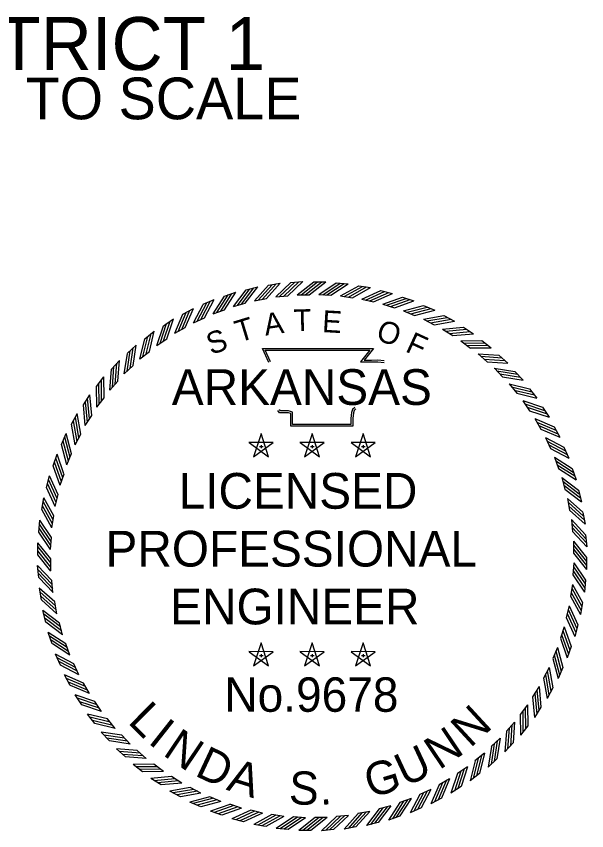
# Model space of a CAD drawing. Extents: x -31696 to 27919, y -8775 to 11152.
# Drawn here: x 13014 to 15598, y -7140 to -3450 of the extents above; entities that cross this region are included whole.
import ezdxf

# ---------------------------------------------------------------- set-up
doc = ezdxf.new("R2010")
doc.units = 0
for name, color, linetype in [('Level 2', 7, 'Continuous'), ('Level 48', 7, 'Continuous'), ('Level 52', 7, 'Continuous')]:
    doc.layers.add(name, color=color, linetype=linetype)

msp = doc.modelspace()

# ---------------------------------------------------------------- linework, layer by layer
at = {"layer": 'Level 52'}
for p, q in [((14055.5, -4689.3), (14108.2, -4675.5)), ((14156.1, -4668.8), (14209.8, -4659.3)), ((14258.1, -4656.6), (14312.3, -4651.6)), ((14361.3, -4653.6), (14415.8, -4653.6)), ((14463.3, -4657.6), (14517.7, -4661.6)), ((14565.2, -4670.9), (14619, -4679.3)), ((13956.9, -4718.2), (14008.3, -4700)), ((14189.4, -4721.2), (14243.8, -4716.1)), ((14286.9, -4711.5), (14341.5, -4711.5)), ((14384.9, -4710), (14439.4, -4714)), ((14482.7, -4716.6), (14536.7, -4725.1)), ((14665.6, -4692.5), (14718.5, -4705.3)), ((14763.9, -4722.3), (14815.6, -4739.5)), ((13861, -4755), (13910.7, -4732.7)), ((13998.3, -4764.3), (14051.1, -4750.4)), ((14093, -4738.8), (14146.7, -4729.3)), ((14579.6, -4731.2), (14632.7, -4744.1)), ((14675, -4753.8), (14726.8, -4771)), ((13768.5, -4799.6), (13816.2, -4773.3)), ((13906.1, -4797.6), (13957.6, -4779.4)), ((14768.2, -4784.2), (14818.4, -4805.6)), ((14859.4, -4760.1), (14909.5, -4781.5)), ((13680, -4851.8), (13725.4, -4821.5)), ((13817, -4838.4), (13866.8, -4816)), ((14858.6, -4822.1), (14906.8, -4847.7)), ((14951.4, -4805.7), (14999.6, -4831.2)), ((13731.5, -4886.4), (13779.3, -4859.9)), ((14945.5, -4867.4), (14991.5, -4896.9)), ((15039.4, -4858.7), (15085.3, -4888.1)), ((13596.1, -4911), (13638.8, -4877.2)), ((13517.4, -4977), (13557.2, -4939.7)), ((13650.3, -4941.2), (13695.8, -4911)), ((15028.4, -4919.8), (15071.8, -4952.9)), ((15122.7, -4918.8), (15166, -4951.9)), ((13573.9, -5002.6), (13616.7, -4968.7)), ((15106.6, -4978.7), (15147.2, -5015.4)), ((13444.4, -5049.2), (13481, -5008.8)), ((15200.7, -4985.6), (15241.1, -5022.1)), ((13502.8, -5070.1), (13542.7, -5032.8)), ((15179.8, -5044), (15217.1, -5083.8)), ((13377.7, -5127.3), (13410.7, -5084)), ((15272.9, -5058.6), (15310.2, -5098.3)), ((13437.6, -5143.3), (13474.2, -5102.8)), ((15247.3, -5115.1), (15281.2, -5157.8)), ((13317.5, -5210.6), (13346.9, -5164.7)), ((15338.9, -5137.3), (15372.8, -5180)), ((13378.6, -5221.6), (13411.8, -5178.2)), ((15308.7, -5191.5), (15339, -5236.9)), ((15398.2, -5221.2), (15428.4, -5266.5)), ((13264.5, -5298.5), (13290, -5250.4)), ((13326.3, -5304.4), (13355.7, -5258.4)), ((15363.6, -5272.7), (15390, -5320.5)), ((15450.3, -5309.7), (15476.7, -5357.4)), ((13218.9, -5390.6), (13240.4, -5340.5)), ((13281, -5391.4), (13306.5, -5343.1)), ((14123.2, -5341), (14089.1, -5445.6)), ((14157.1, -5445.5), (14123.2, -5340.9)), ((14354.3, -5341), (14320.2, -5445.6)), ((14388.2, -5445.5), (14354.4, -5340.9)), ((14585.4, -5341), (14551.3, -5445.6)), ((14619.4, -5445.5), (14585.5, -5340.9)), ((14178.1, -5380.9), (14068.1, -5380.8)), ((14068.2, -5380.9), (14157.2, -5445.7)), ((14089.2, -5445.5), (14178.3, -5381)), ((14409.2, -5380.9), (14299.2, -5380.8)), ((14299.3, -5380.9), (14388.3, -5445.7)), ((14320.3, -5445.5), (14409.4, -5381)), ((14640.4, -5380.9), (14530.4, -5380.8)), ((14530.5, -5380.9), (14619.4, -5445.7)), ((14551.4, -5445.5), (14640.5, -5381)), ((15411.6, -5358.1), (15434, -5407.9)), ((14115.3, -5398.5), (14131.7, -5398.5)), ((14123.3, -5392.6), (14123.3, -5406.4)), ((14346.5, -5398.5), (14362.8, -5398.5)), ((14354.4, -5392.6), (14354.4, -5406.4)), ((14577.6, -5398.5), (14593.9, -5398.5)), ((14585.5, -5392.6), (14585.5, -5406.4)), ((15494.9, -5402.2), (15517.3, -5451.9)), ((13181.1, -5486), (13198.3, -5434.4)), ((13243, -5481.7), (13264.5, -5431.5)), ((15452.3, -5447.3), (15470.5, -5498.8)), ((13151.3, -5584.3), (13164.2, -5531.4)), ((13212.6, -5574.9), (13229.9, -5523.1)), ((15531.8, -5498), (15549.9, -5549.4)), ((15485.6, -5539.5), (15499.5, -5592.3)), ((15560.6, -5596.6), (15574.4, -5649.3)), ((13129.7, -5684.7), (13138.2, -5630.9)), ((13190.1, -5670.3), (13203, -5617.2)), ((15511.1, -5634.1), (15520.6, -5687.9)), ((13175.4, -5767.2), (13183.9, -5713.3)), ((15581.1, -5697.3), (15590.6, -5750.9)), ((13116.5, -5786.6), (13120.5, -5732.3)), ((15528.8, -5730.5), (15533.8, -5784.9)), ((13168.9, -5865), (13172.9, -5810.5)), ((15538.4, -5828.1), (15538.9, -5882.7)), ((15593.3, -5799.2), (15598.3, -5853.5)), ((13111.7, -5889.2), (13111.2, -5834.7)), ((15597.1, -5901.9), (15597.6, -5956.4)), ((13115.5, -5991.8), (13110.5, -5937.6)), ((13170.4, -5963), (13169.9, -5908.4)), ((15539.9, -5926.1), (15535.9, -5980.5)), ((13180, -6060.6), (13175, -6006.2)), ((15592.3, -6004.5), (15588.3, -6058.8)), ((13127.6, -6093.8), (13118.2, -6040.2)), ((15533.3, -6023.9), (15524.9, -6077.8)), ((13197.6, -6157), (13188.2, -6103.2)), ((15518.7, -6120.8), (15505.8, -6173.8)), ((15579.1, -6106.3), (15570.6, -6160.1)), ((13148.2, -6194.4), (13134.3, -6141.8)), ((13223.2, -6251.6), (13209.3, -6198.8)), ((15496.1, -6216.2), (15478.9, -6268)), ((15557.5, -6206.7), (15544.6, -6259.7)), ((13177, -6293), (13158.8, -6241.7)), ((13256.5, -6343.8), (13238.2, -6292.3)), ((14123.2, -6288.6), (14089.1, -6393.2)), ((14157.1, -6393.1), (14123.2, -6288.5)), ((14354.3, -6288.6), (14320.2, -6393.2)), ((14388.2, -6393.1), (14354.4, -6288.5)), ((14585.4, -6288.6), (14551.3, -6393.2)), ((14619.4, -6393.1), (14585.5, -6288.5)), ((15527.7, -6305), (15510.4, -6356.7)), ((13213.9, -6388.9), (13191.5, -6339.2)), ((14178.1, -6328.5), (14068.1, -6328.4)), ((14068.2, -6328.5), (14157.2, -6393.3)), ((14089.2, -6393.1), (14178.3, -6328.6)), ((14123.3, -6340.2), (14123.3, -6354)), ((14409.2, -6328.5), (14299.2, -6328.4)), ((14299.3, -6328.5), (14388.3, -6393.3)), ((14320.3, -6393.1), (14409.4, -6328.6)), ((14354.4, -6340.2), (14354.4, -6354)), ((14640.4, -6328.5), (14530.4, -6328.4)), ((14530.5, -6328.5), (14619.4, -6393.3)), ((14551.4, -6393.1), (14640.5, -6328.6)), ((14585.5, -6340.2), (14585.5, -6354)), ((15465.8, -6309.4), (15444.3, -6359.6)), ((14115.3, -6346.1), (14131.7, -6346.1)), ((14346.5, -6346.1), (14362.8, -6346.1)), ((14577.6, -6346.1), (14593.9, -6346.1)), ((13297.2, -6432.9), (13274.8, -6383.1)), ((15427.8, -6399.7), (15402.3, -6448)), ((15489.8, -6400.5), (15468.4, -6450.6)), ((13258.5, -6481.4), (13232.1, -6433.7)), ((13345.2, -6518.4), (13318.8, -6470.6)), ((15382.5, -6486.6), (15353.1, -6532.6)), ((15444.3, -6492.6), (15418.8, -6540.7)), ((13310.6, -6569.9), (13280.4, -6524.6)), ((13400.1, -6599.6), (13369.8, -6554.2)), ((15330.2, -6569.5), (15297, -6612.9)), ((15391.2, -6580.5), (15361.9, -6626.4)), ((13369.9, -6653.8), (13336, -6611.1)), ((13461.5, -6676), (13427.6, -6633.2)), ((15271.2, -6647.8), (15234.6, -6688.3)), ((15331.1, -6663.8), (15298.1, -6707.1)), ((13435.8, -6732.5), (13398.6, -6692.8)), ((13529, -6747.1), (13491.6, -6707.2)), ((15205.9, -6720.9), (15166.1, -6758.3)), ((15264.4, -6741.8), (15227.8, -6782.3)), ((13508.1, -6805.5), (13467.7, -6769)), ((13602.1, -6812.3), (13561.6, -6775.7)), ((15134.9, -6788.4), (15092.1, -6822.4)), ((15191.4, -6814.1), (15151.6, -6851.4)), ((13586.1, -6872.3), (13542.8, -6839.2)), ((13680.4, -6871.3), (13637, -6838.2)), ((15058.5, -6849.8), (15013, -6880.1)), ((13763.3, -6923.6), (13717.3, -6894.2)), ((15112.6, -6880.1), (15070, -6913.9)), ((13669.4, -6932.4), (13623.5, -6903)), ((14977.3, -6904.7), (14929.5, -6931.2)), ((13757.4, -6985.4), (13709.2, -6959.9)), ((13850.2, -6968.9), (13801.9, -6943.4)), ((14891.8, -6952.7), (14842, -6975.1)), ((15028.8, -6939.3), (14983.4, -6969.5)), ((13849.4, -7031), (13799.3, -7009.6)), ((13940.6, -7006.9), (13890.4, -6985.4)), ((14802.7, -6993.5), (14751.2, -7011.7)), ((14940.3, -6991.4), (14892.6, -7017.8)), ((14033.8, -7037.3), (13982, -7020)), ((14710.5, -7026.7), (14657.6, -7040.6)), ((14847.8, -7036.1), (14798.1, -7058.4)), ((13944.9, -7068.8), (13893.2, -7051.6)), ((14129.1, -7059.9), (14076.1, -7047)), ((14226.1, -7074.5), (14172.1, -7066)), ((14323.9, -7081.1), (14269.4, -7077.1)), ((14421.9, -7079.5), (14367.3, -7080)), ((14519.4, -7069.9), (14465, -7074.9)), ((14615.8, -7052.3), (14562, -7061.8)), ((14751.9, -7072.9), (14700.5, -7091.1)), ((14043.2, -7098.6), (13990.3, -7085.7)), ((14143.6, -7120.2), (14089.8, -7111.7)), ((14653.3, -7101.7), (14600.6, -7115.6)), ((14245.5, -7133.4), (14191.1, -7129.4)), ((14348.1, -7138.2), (14293.6, -7138.7)), ((14450.7, -7134.5), (14396.4, -7139.5)), ((14552.7, -7122.3), (14499, -7131.8))]:
    msp.add_line(p, q, dxfattribs=at)
for points in [[(14015.3, -4760.1), (14072.4, -4685.1)], [(14033.5, -4754.9), (14090.6, -4679.9)], [(14051.1, -4750.4), (14108.2, -4675.4)], [(14092.9, -4738.9), (14156, -4668.8)], [(14110.2, -4736), (14173.3, -4666)], [(14128.8, -4732.3), (14191.9, -4662.3)], [(14146.7, -4729.3), (14209.8, -4659.3)], [(14189.3, -4721.2), (14258, -4656.7)], [(14206.8, -4719.8), (14275.5, -4655.2)], [(14225.6, -4717.6), (14294.3, -4653.1)], [(14243.7, -4716.1), (14312.4, -4651.6)], [(14286.9, -4711.6), (14361.2, -4653.6)], [(14304.4, -4711.8), (14378.7, -4653.8)], [(14323.3, -4711.3), (14397.7, -4653.4)], [(14341.5, -4711.5), (14415.8, -4653.5)], [(14384.9, -4710.1), (14463.2, -4657.7)], [(14402.3, -4711.5), (14480.7, -4659.1)], [(14421.2, -4712.5), (14499.6, -4660.1)], [(14439.3, -4714), (14517.7, -4661.6)], [(14482.6, -4716.6), (14565.1, -4670.9)], [(14499.9, -4719.5), (14582.4, -4673.8)], [(14518.7, -4722), (14601.2, -4676.3)], [(14536.6, -4725), (14619.1, -4679.3)], [(13906.1, -4797.7), (13956.8, -4718.2)], [(13922.7, -4792), (13973.4, -4712.5)], [(13940.4, -4785.3), (13991.1, -4705.8)], [(13957.5, -4779.4), (14008.3, -4699.9)], [(13998.3, -4764.4), (14055.4, -4689.4)], [(14579.6, -4731.2), (14665.5, -4692.5)], [(14596.6, -4735.5), (14682.5, -4696.8)], [(14615, -4739.6), (14701, -4700.9)], [(14632.6, -4744.1), (14718.6, -4705.3)], [(13817, -4838.4), (13861, -4755.1)], [(13833, -4831.4), (13877, -4748)], [(13850.1, -4823.3), (13894.1, -4739.9)], [(13866.7, -4816), (13910.8, -4732.6)], [(14674.9, -4753.8), (14763.8, -4722.3)], [(14691.5, -4759.5), (14780.4, -4728)], [(14709.6, -4765.1), (14798.5, -4733.6)], [(14726.8, -4771), (14815.6, -4739.5)], [(13746.9, -4878.1), (13783.9, -4791.4)], [(13763.3, -4868.6), (13800.3, -4781.8)], [(13779.2, -4859.9), (13816.2, -4773.2)], [(14768.1, -4784.2), (14859.3, -4760.1)], [(14784.2, -4791.2), (14875.3, -4767.2)], [(14801.8, -4798.3), (14892.9, -4774.2)], [(14818.4, -4805.6), (14909.5, -4781.5)], [(13680.5, -4920.9), (13710.2, -4831.4)], [(13695.7, -4911), (13725.4, -4821.5)], [(13731.5, -4886.4), (13768.5, -4799.7)], [(14858.5, -4822.1), (14951.3, -4805.7)], [(14873.9, -4830.5), (14966.7, -4814)], [(14890.8, -4839), (14983.7, -4822.5)], [(14906.8, -4847.6), (14999.6, -4831.1)], [(13650.3, -4941.3), (13680, -4851.8)], [(13665, -4931.7), (13694.7, -4842.3)], [(14945.4, -4867.4), (15039.3, -4858.7)], [(14960.1, -4877), (15054, -4868.3)], [(13587.7, -4992), (13609.9, -4900.3)], [(13602.3, -4979.9), (13624.5, -4888.2)], [(13616.6, -4968.7), (13638.8, -4877.1)], [(14976.3, -4886.9), (15070.1, -4878.1)], [(14991.4, -4896.8), (15085.3, -4888.1)], [(13542.6, -5032.8), (13557.2, -4939.7)], [(13573.9, -5002.7), (13596.1, -4911.1)], [(15028.3, -4919.8), (15122.6, -4918.8)], [(15042.1, -4930.5), (15136.4, -4929.6)], [(15057.4, -4941.7), (15151.7, -4940.7)], [(13502.8, -5070.2), (13517.4, -4977.1)], [(13515.7, -5058.3), (13530.3, -4965.2)], [(13529.3, -5045.1), (13543.8, -4952)], [(14158.3, -5018.2), (14129.2, -4955.3), (14631.7, -4955), (14589.8, -5007.8), (14623.9, -5007.3), (14652.4, -5007), (14680.9, -5010.1)], [(14165.5, -5014.9), (14141.7, -4963.3), (14615.2, -4963), (14573.1, -5016), (14624, -5015.3), (14652, -5014.9), (14680, -5018)], [(15071.7, -4952.8), (15166, -4951.9)], [(15106.6, -4978.7), (15200.6, -4985.6)], [(13474.1, -5102.8), (13481, -5008.8)], [(15119.5, -4990.6), (15213.5, -4997.4)], [(15133.8, -5003), (15227.8, -5009.8)], [(15147.1, -5015.3), (15241.2, -5022.1)], [(13437.6, -5143.4), (13444.4, -5049.3)], [(13449.5, -5130.5), (13456.3, -5036.4)], [(13461.8, -5116.1), (13468.7, -5022.1)], [(15179.7, -5044), (15272.8, -5058.6)], [(13411.7, -5178.2), (13410.7, -5083.9)], [(15191.6, -5056.9), (15284.7, -5071.5)], [(15204.8, -5070.4), (15298, -5085)], [(15217.1, -5083.8), (15310.3, -5098.3)], [(13378.6, -5221.6), (13377.6, -5127.4)], [(13389.4, -5207.8), (13388.4, -5113.5)], [(13400.5, -5192.5), (13399.6, -5098.2)], [(15247.2, -5115), (15338.8, -5137.3)], [(13355.7, -5258.5), (13346.9, -5164.6)], [(15258, -5128.9), (15349.6, -5151.1)], [(15270.1, -5143.5), (15361.7, -5165.7)], [(15281.2, -5157.8), (15372.8, -5180)], [(13335.9, -5289.8), (13327.1, -5196)], [(13345.7, -5273.7), (13337, -5179.8)], [(15308.6, -5191.4), (15398.1, -5221.1)], [(13326.3, -5304.5), (13317.5, -5210.7)], [(14552.6, -5228.8), (14544, -5235.8), (14541.1, -5246.2), (14538.3, -5272.3), (14538.3, -5307), (14257.8, -5307), (14257.8, -5260.1), (14257.8, -5249.7), (14246.4, -5246.2), (14206.5, -5246.2), (14199.4, -5235.4)], [(14547.5, -5222.6), (14537, -5231.2), (14533.3, -5244.7), (14530.3, -5271.8), (14530.3, -5299), (14265.7, -5299), (14265.7, -5260.1), (14265.7, -5243.8), (14247.6, -5238.2), (14210.8, -5238.2), (14206.1, -5231)], [(15318.2, -5206.1), (15407.7, -5235.8)], [(15329, -5221.6), (15418.5, -5251.3)], [(15339, -5236.8), (15428.5, -5266.5)], [(13297.8, -5359.1), (13281.4, -5266.3)], [(13306.5, -5343.1), (13290, -5250.3)], [(15363.5, -5272.6), (15450.2, -5309.6)], [(13281, -5391.4), (13264.5, -5298.6)], [(13289.3, -5376), (13272.9, -5283.2)], [(15371.8, -5288.1), (15458.6, -5325.1)], [(15381.4, -5304.4), (15468.1, -5341.4)], [(13264.4, -5431.6), (13240.4, -5340.4)], [(15390, -5320.4), (15476.7, -5357.4)], [(13250.1, -5465.7), (13226, -5374.6)], [(13257.1, -5448.2), (13233.1, -5357)], [(15411.5, -5358.1), (15494.9, -5402.1)], [(15418.5, -5374.2), (15501.9, -5418.2)], [(13243, -5481.8), (13219, -5390.7)], [(15426.7, -5391.2), (15510, -5435.3)], [(15434, -5407.9), (15517.3, -5451.9)], [(13223.9, -5540.3), (13192.4, -5451.5)], [(13229.8, -5523.1), (13198.3, -5434.3)], [(15452.3, -5447.2), (15531.7, -5498)], [(13212.7, -5575), (13181.1, -5486.1)], [(13218.4, -5558.4), (13186.8, -5469.6)], [(15458, -5463.8), (15537.4, -5514.6)], [(15464.7, -5481.5), (15544.1, -5532.3)], [(13202.9, -5617.3), (13164.2, -5531.3)], [(15470.6, -5498.7), (15550, -5549.4)], [(13194.4, -5653.4), (13155.7, -5567.4)], [(13198.5, -5634.9), (13159.7, -5548.9)], [(15485.5, -5539.4), (15560.5, -5596.6)], [(15489.8, -5556.4), (15564.8, -5613.6)], [(13190.1, -5670.4), (13151.3, -5584.4)], [(15495.1, -5574.6), (15570, -5631.8)], [(15499.5, -5592.2), (15574.5, -5649.4)], [(13183.9, -5713.3), (13138.2, -5630.9)], [(15511.1, -5634), (15581.1, -5697.2)], [(13178.4, -5750), (13132.7, -5667.5)], [(13180.9, -5731.2), (13135.2, -5648.8)], [(15514, -5651.3), (15584, -5714.5)], [(15517.7, -5669.9), (15587.7, -5733.1)], [(13175.5, -5767.3), (13129.8, -5684.8)], [(15520.6, -5687.8), (15590.7, -5751)], [(13171.3, -5828.7), (13119, -5750.3)], [(13172.8, -5810.6), (13120.5, -5732.2)], [(15528.7, -5730.5), (15593.3, -5799.2)], [(15530.2, -5747.9), (15594.7, -5816.6)], [(13168.9, -5865.1), (13116.5, -5786.7)], [(13170.4, -5847.6), (13118, -5769.2)], [(15532.3, -5766.7), (15596.9, -5835.5)], [(15533.8, -5784.8), (15598.4, -5853.5)], [(15538.3, -5828), (15597, -5901.8)], [(13169.9, -5908.5), (13111.2, -5834.7)], [(13169.9, -5926.6), (13111.2, -5852.8)], [(15538.3, -5845.5), (15597, -5919.3)], [(15538.9, -5864.5), (15597.6, -5938.3)], [(13170.4, -5945.5), (13111.8, -5871.7)], [(13170.4, -5963.1), (13111.8, -5889.3)], [(15538.9, -5882.6), (15597.6, -5956.4)], [(13175, -6006.2), (13110.4, -5937.5)], [(15539.9, -5926), (15592.2, -6004.4)], [(13176.5, -6024.3), (13111.9, -5955.6)], [(13178.6, -6043.1), (13114.1, -5974.4)], [(15537.5, -5962.4), (15589.8, -6040.8)], [(15538.4, -5943.5), (15590.8, -6021.9)], [(13180.1, -6060.6), (13115.5, -5991.9)], [(15536, -5980.5), (15588.3, -6058.9)], [(13188.1, -6103.3), (13118.1, -6040.1)], [(15530.4, -6041.1), (15576.1, -6123.5)], [(15533.3, -6023.8), (15579, -6106.2)], [(13191.1, -6121.2), (13121.1, -6058)], [(13194.8, -6139.7), (13124.8, -6076.6)], [(15524.9, -6077.8), (15570.6, -6160.2)], [(15527.9, -6059.8), (15573.6, -6142.3)], [(13197.7, -6157), (13127.7, -6093.9)], [(15518.7, -6120.7), (15557.4, -6206.7)], [(13209.3, -6198.9), (13134.3, -6141.7)], [(13213.7, -6216.5), (13138.7, -6159.3)], [(15510.3, -6156.2), (15549.1, -6242.1)], [(15514.4, -6137.7), (15553.1, -6223.7)], [(13218.9, -6234.7), (13144, -6177.5)], [(13223.3, -6251.7), (13148.3, -6194.5)], [(15505.9, -6173.8), (15544.6, -6259.7)], [(15490.4, -6232.7), (15521.9, -6321.5)], [(15496.1, -6216.1), (15527.6, -6304.9)], [(13238.2, -6292.4), (13158.8, -6241.6)], [(13244.1, -6309.6), (13164.7, -6258.8)], [(15478.9, -6267.9), (15510.5, -6356.8)], [(15484.8, -6250.8), (15516.4, -6339.6)], [(13250.8, -6327.3), (13171.4, -6276.5)], [(13256.5, -6343.8), (13177.1, -6293.1)], [(13274.8, -6383.2), (13191.5, -6339.2)], [(15451.6, -6342.9), (15475.7, -6434)], [(15458.7, -6325.3), (15482.8, -6416.5)], [(15465.7, -6309.3), (15489.8, -6400.4)], [(13282.1, -6399.8), (13198.7, -6355.8)], [(13290.3, -6416.9), (13206.9, -6372.9)], [(15444.4, -6359.5), (15468.4, -6450.7)], [(13297.3, -6433), (13213.9, -6389)], [(15419.4, -6415.1), (15435.9, -6507.9)], [(15427.8, -6399.6), (15444.3, -6492.5)], [(13318.8, -6470.7), (13232.1, -6433.7)], [(13327.4, -6486.7), (13240.7, -6449.7)], [(15402.3, -6447.9), (15418.8, -6540.8)], [(15411, -6432), (15427.4, -6524.8)], [(13336.9, -6503), (13250.2, -6466)], [(13345.3, -6518.4), (13258.6, -6481.4)], [(15382.5, -6486.6), (15391.2, -6580.4)], [(13369.8, -6554.2), (13280.3, -6524.5)], [(15363, -6517.4), (15371.8, -6611.3)], [(15372.9, -6501.2), (15381.6, -6595.1)], [(13379.7, -6569.4), (13290.3, -6539.7)], [(13390.6, -6585), (13301.1, -6555.3)], [(15353.1, -6532.6), (15361.9, -6626.5)], [(13400.2, -6599.6), (13310.7, -6569.9)], [(15308.2, -6598.6), (15309.2, -6692.8)], [(15319.4, -6583.3), (15320.4, -6677.5)], [(15330.2, -6569.4), (15331.1, -6663.7)], [(13427.6, -6633.3), (13335.9, -6611.1)], [(13438.7, -6647.6), (13347.1, -6625.4)], [(13450.8, -6662.2), (13359.2, -6640)], [(15297.1, -6612.9), (15298.1, -6707.2)], [(13461.6, -6676), (13370, -6653.8)], [(15246.9, -6674.9), (15240.1, -6769)], [(15259.3, -6660.6), (15252.5, -6754.6)], [(15271.2, -6647.7), (15264.4, -6741.7)], [(13491.7, -6707.3), (13398.5, -6692.7)], [(13503.9, -6720.7), (13410.8, -6706.1)], [(15234.6, -6688.3), (15227.8, -6782.3)], [(13517.2, -6734.2), (13424.1, -6719.6)], [(13529.1, -6747.1), (13435.9, -6732.5)], [(15179.5, -6746), (15165, -6839.1)], [(15193, -6732.7), (15178.5, -6825.9)], [(15205.9, -6720.9), (15191.4, -6814)], [(13561.6, -6775.8), (13467.6, -6769)], [(13575, -6788.1), (13481, -6781.3)], [(15166.2, -6758.3), (15151.6, -6851.4)], [(13589.3, -6800.5), (13495.3, -6793.6)], [(13602.2, -6812.3), (13508.2, -6805.5)], [(15092.2, -6822.4), (15069.9, -6914)], [(15106.5, -6811.2), (15084.3, -6902.8)], [(15121, -6799.1), (15098.8, -6890.7)], [(15134.9, -6788.4), (15112.7, -6880)], [(13637, -6838.2), (13542.8, -6839.2)], [(13651.4, -6849.4), (13557.1, -6850.4)], [(13666.7, -6860.5), (13572.4, -6861.5)], [(15043.8, -6859.3), (15014.1, -6948.8)], [(15058.5, -6849.8), (15028.8, -6939.2)], [(13680.5, -6871.3), (13586.2, -6872.3)], [(13717.3, -6894.3), (13623.5, -6903)], [(15013.1, -6880.1), (14983.4, -6969.6)], [(15028.3, -6870.2), (14998.6, -6959.7)], [(13732.5, -6904.2), (13638.7, -6912.9)], [(13748.7, -6914), (13654.8, -6922.8)], [(13763.4, -6923.6), (13669.5, -6932.4)], [(14929.5, -6931.2), (14892.6, -7017.9)], [(14945.5, -6922.5), (14908.5, -7009.2)], [(14961.9, -6913), (14924.9, -6999.7)], [(14977.3, -6904.6), (14940.3, -6991.4)], [(13802, -6943.5), (13709.2, -6959.9)], [(13817.9, -6952.1), (13725.1, -6968.6)], [(13834.9, -6960.6), (13742, -6977)], [(13850.3, -6968.9), (13757.5, -6985.4)], [(14858.7, -6967.8), (14814.7, -7051.2)], [(14875.8, -6959.7), (14831.7, -7043)], [(14891.8, -6952.6), (14847.8, -7036)], [(13890.4, -6985.5), (13799.3, -7009.6)], [(13907, -6992.8), (13815.9, -7016.9)], [(13924.6, -6999.8), (13833.4, -7023.9)], [(13940.7, -7006.9), (13849.5, -7031)], [(14768.4, -7005.8), (14717.7, -7085.2)], [(14786.1, -6999.1), (14735.4, -7078.5)], [(14802.7, -6993.4), (14751.9, -7072.8)], [(14842.1, -6975.1), (14798, -7058.5)], [(13982, -7020.1), (13893.2, -7051.6)], [(13999.2, -7026), (13910.3, -7057.5)], [(14017.3, -7031.6), (13928.4, -7063.1)], [(14033.8, -7037.3), (13945, -7068.8)], [(14657.7, -7040.7), (14600.6, -7115.6)], [(14675.3, -7036.2), (14618.2, -7111.2)], [(14693.5, -7031), (14636.4, -7106)], [(14710.5, -7026.7), (14653.4, -7101.7)], [(14751.2, -7011.7), (14700.5, -7091.1)], [(14076.1, -7047), (13990.2, -7085.8)], [(14093.7, -7051.5), (14007.8, -7090.2)], [(14112.2, -7055.5), (14026.3, -7094.3)], [(14129.2, -7059.8), (14043.3, -7098.6)], [(14172.2, -7066), (14089.7, -7111.8)], [(14190.1, -7069), (14107.6, -7114.7)], [(14208.8, -7071.6), (14126.4, -7117.3)], [(14226.1, -7074.5), (14143.7, -7120.2)], [(14269.5, -7077.1), (14191.1, -7129.5)], [(14287.5, -7078.6), (14209.2, -7131)], [(14306.5, -7079.6), (14228.1, -7131.9)], [(14323.9, -7081), (14245.5, -7133.4)], [(14367.3, -7080.1), (14293.5, -7138.7)], [(14385.5, -7080.1), (14311.7, -7138.7)], [(14404.4, -7079.5), (14330.6, -7138.1)], [(14421.9, -7079.5), (14348.1, -7138.1)], [(14465.1, -7075), (14396.4, -7139.5)], [(14483.2, -7073.5), (14414.5, -7138)], [(14502, -7071.3), (14433.3, -7135.9)], [(14519.5, -7069.9), (14450.8, -7134.4)], [(14562.1, -7061.8), (14499, -7131.8)], [(14580, -7058.8), (14516.9, -7128.8)], [(14598.6, -7055.1), (14535.4, -7125.1)], [(14615.9, -7052.2), (14552.7, -7122.2)]]:
    msp.add_lwpolyline(points, dxfattribs=at)

# ---------------------------------------------------------------- texts
at = {"layer": 'Level 2'}
msp.add_text('NOT TO SCALE', height=189, dxfattribs=at).set_placement((12452.2, -3916.8))
at = {"layer": 'Level 48'}
msp.add_text('DISTRICT 1', height=240, dxfattribs=at).set_placement((12393.3, -3693.8))
at = {"layer": 'Level 52'}
for s, height, rotation, p in [('A', 99.1, 8.6788, (14142.9, -4897.3)), ('T', 99.1, 1.4789, (14271, -4877.5)), ('E', 99.1, 356.672, (14397.8, -4880.5)), ('T', 99.1, 16.9015, (14022.6, -4928.7)), ('O', 99.1, 341.2218, (14638.5, -4914.5)), ('S', 99.1, 19.7726, (13896.6, -4985.3)), ('F', 99.1, 335.3628, (14772.1, -4966.8)), ('L', 150.5, 315.1295, (13514.7, -6648.7)), ('N', 150.5, 42.6817, (15070.7, -6767.7)), ('I', 150.5, 321.696, (13606.3, -6739.9)), ('N', 150.5, 33.9264, (14929.7, -6866.5)), ('N', 150.5, 326.0736, (13672.9, -6794.5)), ('U', 150.5, 25.1712, (14775.3, -6942.7)), ('D', 150.5, 334.8288, (13817.6, -6887.9)), ('G', 150.5, 16.7808, (14618.1, -6992.9)), ('A', 150.5, 342.8544, (13961.3, -6953.2)), ('S', 150.5, 357.8112, (14247.4, -7018.9)), ('.', 150.5, 5.1072, (14390.8, -7023.5))]:
    msp.add_text(s, height=height, rotation=rotation, dxfattribs=at).set_placement(p)
for s, height, p in [('ARKANSAS', 161.78, (13718.4, -5210.7)), ('LICENSED', 161.78, (13749.3, -5680.9)), ('PROFESSIONAL', 161.779, (13418, -5942.9)), ('ENGINEER', 161.78, (13710.7, -6204.8)), ('No.9678', 156, (13956.6, -6600.8))]:
    msp.add_text(s, height=height, dxfattribs=at).set_placement(p)

doc.saveas('drawing.dxf')
